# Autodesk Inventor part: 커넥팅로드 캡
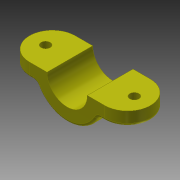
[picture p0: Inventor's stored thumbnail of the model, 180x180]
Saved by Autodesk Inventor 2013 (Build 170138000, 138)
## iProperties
Created: 2017-05
Part Number: 커넥팅로드 캡
Material: 강철, 탄소
Document SubType Name: Modeling
Designer: mduedu
Density: 7.87 g/cm^3
Mass: 31.5627 g
Surface Area: 22.8316 cm^2
Volume: 4.0105 cm^3
Author: mduedu
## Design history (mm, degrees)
sketch "스케치1"
  geometry: L1 (22.5, 0)-(22.5, -5); L2 (-22.5, -5)-(-22.5, 0); L3 (-22.5, 0)-(-7.5, 0); L4 (7.5, 0)-(22.5, 0); L5 (22.5, -5)-(11.456, -5); L6 (-11.456, -5)-(-22.5, -5); A1 r 7.5 centre (0, 0) between (-7.5, 0) and (7.5, 0); A2 r 12.5 centre (0, 0) between (-11.456, -5) and (11.456, -5); 2 further points
  constraints: 12 end point, 5 parallel, 4 point on circle, 3 coincident, 2 centre point, 2 collinear, 2 horizontal, 2 horizontal alignment, 2 perpendicular
  dimensions: "d0" = 45 distance of L2.end L1.start; "d2" = 5 distance of L2.start L2.end; "d3" = 15 diameter of A1; "d4" = 25 diameter of A2
extrude "돌출1" new body sketch "스케치1" stored distance "d5" = 17; taper "d6" = 0 deg
fillet "모깎기1"
fillet "모깎기2"
fillet "모깎기3" dims "d11" = 2
fillet "모깎기4" dims "d12" = 1
sketch "스케치4"
  geometry: 2 further points
  constraints: 2 other
hole "구멍1" sketch "스케치4" at (30.5, 7.5), (-2.5, 7.5) diameter "d19" = 3.4; stored, may be unused: countersink angle "d23" = 90 deg, drill point angle "d25" = 0 deg; dims "d20" = 6, "d21" = 4, "d22" = 2, "d24" = 8
node "솔리드1"
